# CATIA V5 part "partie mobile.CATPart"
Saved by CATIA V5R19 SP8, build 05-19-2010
Part number: partie mobile
Bounding box of the stored display mesh (mm): x 39.974 to 49.509, y -47 to 47, z 26.217 to 87
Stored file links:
  G:\EU_thinkMotion\CFAO_2010\MMS_groupe1\MMS_groupe1\A reprendre\OK\glenerrant\glenerrant\glenerrant\partie mobile.CATPart
  G:\EU_thinkMotion\CFAO_2010\MMS_groupe1\MMS_groupe1\A reprendre\OK\glenerrant\glenerrant\glenerrant\Corps verin3.CATPart
  C:\Users\Gauthier\Documents\IFMA\Projet CFAO\Systeme.CATProduct
  G:\EU_thinkMotion\CFAO_2010\MMS_groupe1\MMS_groupe1\A reprendre\OK\glenerrant\glenerrant\glenerrant\Tige verin2.CATPart
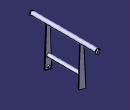
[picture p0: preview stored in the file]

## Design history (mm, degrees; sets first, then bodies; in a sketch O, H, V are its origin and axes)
Set1
  Line1: linked copy from another document
Set2
  Point1: (45, -23, 32)
  Point2: (45, 23, 32)
  Point3: (45, 0, 45)
  Point4: (45, 0, 45)
  Point5: (17, 0, 101)
Body1 (main body)
  Sketch1 on zx-plane, origin (0, 0, 0), H (-1, 0, 0), V (0, 0, 1)
    circle A1 centre (-45, 45) radius 2.5
    point P1 (-45, 45)
    reference projected point E1 (-45, 45) from Point3
    radius A1 = 2.5
    coincidence: P1 E1
  Pad1: profile Sketch1, direction (0, 1, 0), length 23, opposite side length 23
  Sketch2 on end face of Pad1, origin (0, 23, 0), H (-1, 0, 0), V (0, 0, 1)
    line L1 (-49.5093, 29.2296) -> (-47.4961, 82.1914)
    line L2 (-49.5093, 29.2296) -> (-39.9737, 26.2174)
    line L3 (-39.9737, 26.2174) -> (-42.4962, 82.1605)
    line L4 (-47.4961, 82.1914) -> (-42.4962, 82.1605)
    reference projected point E1 (-45, 32) from Point2
    reference projected point E2 (-45, 32) from Point2
    length L3 = 56
    length L1 = 53
    length L4 = 5
    length L2 = 10
    distance E1 L2 = 4
    distance E2 L1 = 4.4008
  Pad2: profile Sketch2, direction (0, 1, 0), length 1
  Sketch3 on start face of Pad1, origin (0, -23, 0), H (1, 0, 0), V (0, 0, 1)
    line L1 (49.5093, 29.2296) -> (47.4961, 82.1914)
    point P1 (49.5093, 29.2296)
    line L2 (49.5093, 29.2296) -> (39.9737, 26.2174)
    point P3 (39.9737, 26.2174)
    reference projected line E1 (49.5093, 29.2296) -> (39.9737, 26.2174) from Sketch2.L2
    reference projected line E2 (47.4961, 82.1914) -> (49.5093, 29.2296) from Sketch2.L1
    point P4 (42.4962, 82.1605)
    line L3 (47.4961, 82.1914) -> (42.4962, 82.1605)
    reference projected line E3 (42.4962, 82.1605) -> (47.4961, 82.1914) from Sketch2.L4
    line L4 (39.9737, 26.2174) -> (42.4962, 82.1605)
    reference projected line E4 (39.9737, 26.2174) -> (42.4962, 82.1605) from Sketch2.L3
    reference projected point E5 (39.9737, 26.2174) from vertex [element of Sketch2 | element of Sketch2]
    reference projected point E6 (42.4962, 82.1605) from vertex [element of Sketch2 | element of Sketch2]
    reference projected point E7 (49.5093, 29.2296) from vertex [element of Sketch2 | element of Sketch2]
    parallelism: E1 L2, L1 E2, E3 L3, L4 E4
    coincidence: P3 E5, P4 E6, P1 E7
  Pad3: profile Sketch3, direction (0, -1, 0), length 1
  Sketch4 on zx-plane, origin (0, 0, 0), H (-1, 0, 0), V (0, 0, 1)
    circle A1 centre (-45.0418, 84) radius 3
    point P1 (-45.0418, 84)
    reference projected point E1 (-45, 45) from Point3
    reference projected point E2 (-17, 101) from Point5
    radius A1 = 3
    distance E1 P1 = 39
    distance P1 E2 = 32.7924
  Pad4: profile Sketch4, direction (0, 1, 0), length 45, opposite side length 45
  Sketch5 on start face of Pad2, origin (0, 23, 0), H (1, 0, 0), V (0, 0, 1)
    circle A1 centre (45, 32) radius 2
    point P1 (45, 32)
    reference projected point E1 (45, 32) from Point2
    radius A1 = 2
    coincidence: P1 E1
  Pad5: profile Sketch5, direction (0, -1, 0), length 2
  Sketch6 on start face of Pad3, origin (0, -23, 0), H (-1, 0, 0), V (0, 0, 1)
    circle A1 centre (-45, 32) radius 2
    point P1 (-45, 32)
    reference projected point E1 (-45, 32) from Point1
    radius A1 = 2
    coincidence: P1 E1
  Pad6: profile Sketch6, direction (0, 1, 0), length 2
  Sketch7 on end face of Pad4, origin (0, 45, 0), H (-1, 0, 0), V (0, 0, 1)
    point P1 (-47.6376, 82.4961)
    line L1 (-47.6376, 82.4961) -> (-45.0463, 87)
    line L2 (-45.0463, 87) -> (-42.4459, 85.5039)
    line L3 (-42.4459, 85.5039) -> (-45.0372, 81)
    line L4 (-45.0372, 81) -> (-47.6376, 82.4961)
    point P2 (-45.0463, 87)
    point P3 (-42.4459, 85.5039)
    point P4 (-45.0372, 81)
    reference projected line E1 (-89, 8) -> (-5, 154) from Line1
    reference projected circle E2 centre (-45.0418, 84) radius 3 from edge [face of Pad4 from Sketch4.A1 | end face of Pad4]
    reference projected circle E3 centre (-45.0418, 84) radius 3 from edge [face of Pad4 from Sketch4.A1 | end face of Pad4]
    reference projected circle E4 centre (-45.0418, 84) radius 3 from edge [face of Pad4 from Sketch4.A1 | end face of Pad4]
    reference projected circle E5 centre (-45.0418, 84) radius 3 from edge [face of Pad4 from Sketch4.A1 | end face of Pad4]
    length L2 = 3
    parallelism: L1 E1, L3 L1
    perpendicularity: L2 L3, L3 L4
    coincidence: P2 E2, P3 E3, P4 E4, P1 E5
  Pad7: profile Sketch7, direction (0, 1, 0), length 2
  Sketch8 on start face of Pad4, origin (0, -45, 0), H (1, 0, 0), V (0, 0, 1)
    point P1 (45.0463, 87)
    line L1 (45.0463, 87) -> (47.6376, 82.4961)
    line L2 (47.6376, 82.4961) -> (45.0372, 81)
    line L3 (45.0372, 81) -> (42.4459, 85.5039)
    line L4 (42.4459, 85.5039) -> (45.0463, 87)
    point P2 (47.6376, 82.4961)
    point P3 (45.0372, 81)
    point P4 (42.4459, 85.5039)
    reference projected line E1 (89, 8) -> (5, 154) from Line1
    reference projected circle E2 centre (45.0418, 84) radius 3 from edge [start face of Pad4 | face of Pad4 from Sketch4.A1]
    reference projected circle E3 centre (45.0418, 84) radius 3 from edge [start face of Pad4 | face of Pad4 from Sketch4.A1]
    reference projected circle E4 centre (45.0418, 84) radius 3 from edge [start face of Pad4 | face of Pad4 from Sketch4.A1]
    reference projected circle E5 centre (45.0418, 84) radius 3 from edge [start face of Pad4 | face of Pad4 from Sketch4.A1]
    length L4 = 3
    perpendicularity: L2 L1, L3 L2
    parallelism: L4 L2, L3 E1
    coincidence: P4 E2, P1 E3, P2 E4, P3 E5
  Pad8: profile Sketch8, direction (0, -1, 0), length 2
